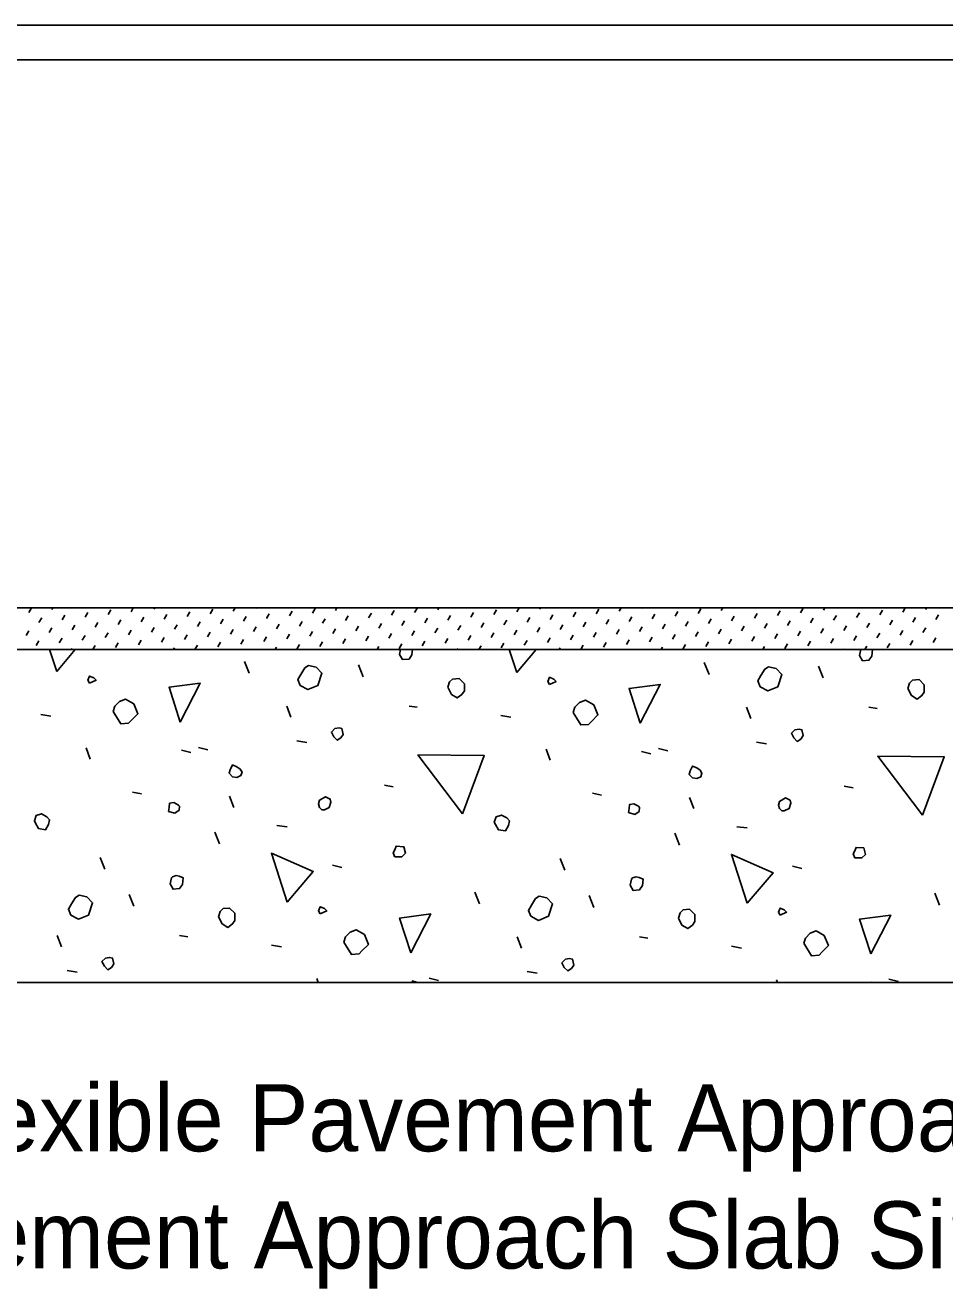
# Model space of a CAD drawing. Extents: x 0.5 to 40.8, y 1 to 25.8.
# Drawn here: x 26.642 to 29.406, y 9.64 to 13.435 of the extents above; entities that cross this region are included whole.
import ezdxf

# ---------------------------------------------------------------- set-up
doc = ezdxf.new("R2010")
doc.units = 0
for name, color, linetype in [('Dimension', 7, 'Continuous'), ('Miscellaneous', 7, 'Continuous'), ('TrafBarrierConc', 7, 'Continuous')]:
    doc.layers.add(name, color=color, linetype=linetype)

msp = doc.modelspace()

# ---------------------------------------------------------------- linework, layer by layer
at = {"layer": 'Miscellaneous'}
for p, q in [((26.6529, 11.6714), (26.6606, 11.6848)), ((26.6834, 11.6409), (26.6915, 11.6549)), ((26.7221, 11.6796), (26.7251, 11.6848)), ((26.7526, 11.649), (26.7607, 11.663)), ((26.8218, 11.6571), (26.8299, 11.6711)), ((26.8909, 11.6652), (26.899, 11.6792)), ((26.9601, 11.6733), (26.9667, 11.6848)), ((26.9906, 11.6428), (26.9987, 11.6568)), ((27.0293, 11.6814), (27.0312, 11.6848)), ((27.0598, 11.6509), (27.0679, 11.6649)), ((27.129, 11.659), (27.1371, 11.673)), ((27.1981, 11.6671), (27.2062, 11.6811)), ((27.2673, 11.6752), (27.2728, 11.6848)), ((27.2978, 11.6447), (27.3059, 11.6587)), ((27.3365, 11.6833), (27.3373, 11.6848)), ((27.367, 11.6528), (27.3751, 11.6668)), ((27.4361, 11.6609), (27.4442, 11.6749)), ((27.5053, 11.669), (27.5134, 11.683)), ((27.5358, 11.6385), (27.5439, 11.6524)), ((27.5745, 11.6771), (27.5789, 11.6848)), ((27.605, 11.6466), (27.6131, 11.6605)), ((27.6742, 11.6547), (27.6823, 11.6686)), ((27.7433, 11.6628), (27.7514, 11.6768)), ((27.8125, 11.6709), (27.8206, 11.6848)), ((27.843, 11.6403), (27.8511, 11.6543)), ((27.8817, 11.679), (27.885, 11.6848)), ((27.9122, 11.6484), (27.9203, 11.6624)), ((27.9814, 11.6565), (27.9895, 11.6705)), ((28.0505, 11.6646), (28.0586, 11.6786)), ((28.1197, 11.6727), (28.1267, 11.6848)), ((28.1502, 11.6422), (28.1583, 11.6562)), ((28.1888, 11.6808), (28.1911, 11.6848)), ((28.2194, 11.6503), (28.2275, 11.6643)), ((28.2885, 11.6584), (28.2966, 11.6724)), ((28.3577, 11.6665), (28.3658, 11.6805)), ((28.4269, 11.6746), (28.4328, 11.6848)), ((28.4574, 11.6441), (28.4655, 11.6581)), ((28.496, 11.6827), (28.4972, 11.6848)), ((28.5266, 11.6522), (28.5347, 11.6662)), ((28.5957, 11.6603), (28.6038, 11.6743)), ((28.6649, 11.6684), (28.673, 11.6824)), ((28.6954, 11.6379), (28.7035, 11.6519)), ((28.7341, 11.6765), (28.7389, 11.6848)), ((28.7646, 11.646), (28.7727, 11.66)), ((28.8032, 11.6846), (28.8033, 11.6848)), ((28.8337, 11.6541), (28.8419, 11.6681)), ((28.9029, 11.6622), (28.911, 11.6762)), ((28.9721, 11.6703), (28.9802, 11.6843)), ((29.0026, 11.6397), (29.0107, 11.6537)), ((29.0412, 11.6784), (29.045, 11.6848)), ((29.0718, 11.6478), (29.0799, 11.6618)), ((29.1409, 11.6559), (29.149, 11.6699)), ((29.2101, 11.664), (29.2182, 11.678)), ((29.2793, 11.6721), (29.2866, 11.6848)), ((29.3098, 11.6416), (29.3179, 11.6556)), ((29.3484, 11.6803), (29.3511, 11.6848)), ((29.379, 11.6497), (29.3871, 11.6637)), ((26.6448, 11.6023), (26.6529, 11.6163)), ((26.714, 11.6104), (26.7221, 11.6244)), ((26.7831, 11.6185), (26.7912, 11.6325)), ((26.8523, 11.6266), (26.8604, 11.6406)), ((26.9215, 11.6347), (26.9296, 11.6487)), ((26.952, 11.6042), (26.9601, 11.6182)), ((27.0212, 11.6123), (27.0293, 11.6263)), ((27.0903, 11.6204), (27.0984, 11.6344)), ((27.1595, 11.6285), (27.1676, 11.6425)), ((27.2287, 11.6366), (27.2368, 11.6506)), ((27.2592, 11.606), (27.2673, 11.62)), ((27.3283, 11.6141), (27.3365, 11.6281)), ((27.3975, 11.6222), (27.4056, 11.6362)), ((27.4667, 11.6303), (27.4748, 11.6443)), ((27.4972, 11.5998), (27.5053, 11.6138)), ((27.5664, 11.6079), (27.5745, 11.6219)), ((27.6355, 11.616), (27.6436, 11.63)), ((27.7047, 11.6241), (27.7128, 11.6381)), ((27.7739, 11.6322), (27.782, 11.6462)), ((27.8044, 11.6017), (27.8125, 11.6157)), ((27.8736, 11.6098), (27.8817, 11.6238)), ((27.9427, 11.6179), (27.9508, 11.6319)), ((28.0119, 11.626), (28.02, 11.64)), ((28.081, 11.6341), (28.0892, 11.6481)), ((28.1116, 11.6036), (28.1197, 11.6176)), ((28.1807, 11.6117), (28.1888, 11.6257)), ((28.2499, 11.6198), (28.258, 11.6338)), ((28.3191, 11.6279), (28.3272, 11.6419)), ((28.3882, 11.636), (28.3963, 11.65)), ((28.4188, 11.6055), (28.4269, 11.6194)), ((28.4879, 11.6136), (28.496, 11.6275)), ((28.5571, 11.6217), (28.5652, 11.6357)), ((28.6263, 11.6298), (28.6344, 11.6438)), ((28.6568, 11.5992), (28.6649, 11.6132)), ((28.726, 11.6073), (28.7341, 11.6213)), ((28.7951, 11.6154), (28.8032, 11.6294)), ((28.8643, 11.6235), (28.8724, 11.6375)), ((28.9334, 11.6316), (28.9415, 11.6456)), ((28.964, 11.6011), (28.9721, 11.6151)), ((29.0331, 11.6092), (29.0412, 11.6232)), ((29.1023, 11.6173), (29.1104, 11.6313)), ((29.1715, 11.6254), (29.1796, 11.6394)), ((29.2406, 11.6335), (29.2487, 11.6475)), ((29.2712, 11.603), (29.2793, 11.617)), ((29.3403, 11.6111), (29.3484, 11.6251)), ((26.6753, 11.5718), (26.6834, 11.5857)), ((26.7445, 11.5799), (26.7526, 11.5939)), ((26.8137, 11.588), (26.8218, 11.602)), ((26.8828, 11.5961), (26.8909, 11.6101)), ((26.9134, 11.5655), (26.9215, 11.5795)), ((26.9825, 11.5736), (26.9906, 11.5876)), ((27.0517, 11.5817), (27.0598, 11.5957)), ((27.1209, 11.5898), (27.129, 11.6038)), ((27.19, 11.5979), (27.1981, 11.6119)), ((27.2206, 11.5674), (27.2287, 11.5814)), ((27.2897, 11.5755), (27.2978, 11.5895)), ((27.3589, 11.5836), (27.367, 11.5976)), ((27.428, 11.5917), (27.4361, 11.6057)), ((27.4586, 11.5612), (27.4667, 11.5752)), ((27.5277, 11.5693), (27.5358, 11.5833)), ((27.5969, 11.5774), (27.605, 11.5914)), ((27.6661, 11.5855), (27.6742, 11.5995)), ((27.7352, 11.5936), (27.7433, 11.6076)), ((27.7658, 11.5631), (27.7739, 11.5771)), ((27.8349, 11.5712), (27.843, 11.5852)), ((27.9041, 11.5793), (27.9122, 11.5933)), ((27.9733, 11.5874), (27.9814, 11.6014)), ((28.0424, 11.5955), (28.0505, 11.6095)), ((28.0729, 11.5649), (28.081, 11.5789)), ((28.1421, 11.573), (28.1502, 11.587)), ((28.2113, 11.5811), (28.2194, 11.5951)), ((28.2804, 11.5892), (28.2885, 11.6032)), ((28.3496, 11.5973), (28.3577, 11.6113)), ((28.3801, 11.5668), (28.3882, 11.5808)), ((28.4493, 11.5749), (28.4574, 11.5889)), ((28.5185, 11.583), (28.5266, 11.597)), ((28.5876, 11.5911), (28.5957, 11.6051)), ((28.6873, 11.5687), (28.6954, 11.5827)), ((28.7565, 11.5768), (28.7646, 11.5908)), ((28.8256, 11.5849), (28.8337, 11.5989)), ((28.8948, 11.593), (28.9029, 11.607)), ((28.9253, 11.5625), (28.9334, 11.5765)), ((28.9945, 11.5706), (29.0026, 11.5846)), ((29.0637, 11.5787), (29.0718, 11.5927)), ((29.1328, 11.5868), (29.1409, 11.6008)), ((29.202, 11.5949), (29.2101, 11.6089)), ((29.2325, 11.5644), (29.2406, 11.5783)), ((29.3017, 11.5725), (29.3098, 11.5864)), ((29.3709, 11.5806), (29.379, 11.5946)), ((26.7811, 11.5598), (26.7831, 11.5633)), ((26.8456, 11.5598), (26.8523, 11.5714)), ((27.0872, 11.5598), (27.0903, 11.5652)), ((27.1517, 11.5598), (27.1595, 11.5733)), ((27.3933, 11.5598), (27.3975, 11.5671)), ((27.6349, 11.5598), (27.6355, 11.5609)), ((27.6994, 11.5598), (27.7047, 11.569)), ((27.941, 11.5598), (27.9427, 11.5627)), ((28.0055, 11.5598), (28.0119, 11.5708)), ((28.2471, 11.5598), (28.2499, 11.5646)), ((28.3116, 11.5598), (28.3191, 11.5727)), ((28.5532, 11.5598), (28.5571, 11.5665)), ((28.6182, 11.5606), (28.6263, 11.5746)), ((28.7948, 11.5598), (28.7951, 11.5603)), ((28.8593, 11.5598), (28.8643, 11.5684)), ((29.1009, 11.5598), (29.1023, 11.5621)), ((29.1654, 11.5598), (29.1715, 11.5702)), ((27.3148, 11.4887), (27.3006, 11.524)), ((27.6577, 11.4781), (27.6436, 11.5134)), ((28.6972, 11.4851), (28.683, 11.5205)), ((29.0401, 11.4745), (29.026, 11.5099)), ((27.4403, 11.3561), (27.4279, 11.3897)), ((27.7956, 11.3897), (27.8204, 11.3861)), ((28.8227, 11.3526), (28.8103, 11.3861)), ((29.178, 11.3861), (29.2028, 11.3826)), ((26.689, 11.3649), (26.7191, 11.3596)), ((28.0714, 11.3614), (28.1014, 11.3561)), ((27.458, 11.2854), (27.488, 11.2801)), ((28.8404, 11.2818), (28.8704, 11.2765)), ((26.8375, 11.2306), (26.8251, 11.2642)), ((27.1115, 11.2571), (27.1398, 11.25)), ((27.1628, 11.2659), (27.191, 11.2589)), ((28.2199, 11.227), (28.2075, 11.2606)), ((28.4939, 11.2536), (28.5222, 11.2465)), ((28.5452, 11.2624), (28.5734, 11.2553)), ((26.9648, 11.1316), (26.9913, 11.1263)), ((27.7214, 11.1528), (27.7479, 11.1475)), ((28.3472, 11.1281), (28.3737, 11.1227)), ((29.1038, 11.1493), (29.1303, 11.144)), ((27.2688, 11.0856), (27.2565, 11.1192)), ((28.6512, 11.0821), (28.6388, 11.1157)), ((27.2264, 10.976), (27.2123, 11.0114)), ((27.3979, 11.0308), (27.4297, 11.0273)), ((28.6088, 10.9725), (28.5947, 11.0078)), ((28.7803, 11.0273), (28.8121, 11.0238)), ((26.8817, 10.9), (26.8675, 10.9354)), ((28.2641, 10.8965), (28.2499, 10.9318)), ((27.5658, 10.9124), (27.5941, 10.9053)), ((28.9482, 10.9089), (28.9765, 10.9018)), ((26.9683, 10.7886), (26.9542, 10.824)), ((28.0078, 10.7957), (27.9936, 10.8311)), ((28.3507, 10.7851), (28.3366, 10.8205)), ((29.3901, 10.7922), (29.376, 10.8275)), ((26.7509, 10.6667), (26.7385, 10.7003)), ((27.1062, 10.7003), (27.1309, 10.6967)), ((27.382, 10.672), (27.412, 10.6667)), ((28.1333, 10.6631), (28.1209, 10.6967)), ((28.4886, 10.6967), (28.5133, 10.6932)), ((28.7644, 10.6684), (28.7944, 10.6631)), ((26.7685, 10.596), (26.7986, 10.5907)), ((28.1509, 10.5924), (28.181, 10.5871)), ((27.5223, 10.5598), (27.5181, 10.5712)), ((27.8045, 10.5641), (27.8218, 10.5598)), ((27.8557, 10.573), (27.884, 10.5659)), ((28.9034, 10.5598), (28.9005, 10.5677)), ((29.1869, 10.5606), (29.1901, 10.5598)), ((29.2381, 10.5694), (29.2664, 10.5624))]:
    msp.add_line(p, q, dxfattribs=at)
for points in [[(26.7367, 11.494), (26.7153, 11.5598)], [(26.7924, 11.5598), (26.7367, 11.494)], [(27.7673, 11.5452), (27.7762, 11.5293), (27.7956, 11.5311), (27.8045, 11.5435), (27.8059, 11.5598)], [(27.7702, 11.5598), (27.7673, 11.5452)], [(28.1191, 11.4904), (28.0966, 11.5598)], [(28.1778, 11.5598), (28.1191, 11.4904)], [(29.1497, 11.5417), (29.1586, 11.5258), (29.178, 11.5276), (29.1869, 11.5399), (29.1886, 11.5594), (29.1877, 11.5598)], [(29.1537, 11.5598), (29.1533, 11.5594), (29.1497, 11.5417)], [(27.4686, 11.4516), (27.4916, 11.4392), (27.5216, 11.4516), (27.534, 11.4887), (27.5163, 11.5064), (27.4933, 11.5117), (27.4827, 11.5046), (27.4704, 11.4851), (27.4615, 11.4692), (27.4686, 11.4516)], [(28.851, 11.448), (28.874, 11.4356), (28.904, 11.448), (28.9164, 11.4851), (28.8987, 11.5028), (28.8757, 11.5081), (28.8651, 11.5011), (28.8527, 11.4816), (28.8439, 11.4657), (28.851, 11.448)], [(26.8357, 11.4586), (26.8552, 11.4675), (26.8481, 11.4745), (26.8357, 11.4798), (26.8304, 11.4675), (26.8357, 11.4586)], [(27.9123, 11.4463), (27.9229, 11.425), (27.9406, 11.4144), (27.9547, 11.425), (27.9618, 11.4356), (27.9618, 11.4569), (27.9459, 11.4728), (27.9264, 11.471), (27.9176, 11.4622), (27.9123, 11.4463)], [(28.2181, 11.4551), (28.2376, 11.4639), (28.2305, 11.471), (28.2181, 11.4763), (28.2128, 11.4639), (28.2181, 11.4551)], [(29.2947, 11.4427), (29.3053, 11.4215), (29.323, 11.4109), (29.3371, 11.4215), (29.3442, 11.4321), (29.3442, 11.4533), (29.3283, 11.4692), (29.3088, 11.4675), (29.3, 11.4586), (29.2947, 11.4427)], [(27.108, 11.342), (27.0744, 11.4463), (27.1681, 11.4586), (27.108, 11.342)], [(28.4904, 11.3384), (28.4568, 11.4427), (28.5505, 11.4551), (28.4904, 11.3384)], [(26.9064, 11.3738), (26.9294, 11.3366), (26.9524, 11.3384), (26.9612, 11.3473), (26.9807, 11.3667), (26.9683, 11.3968), (26.9436, 11.4109), (26.9259, 11.4038), (26.9117, 11.3897), (26.9064, 11.3738)], [(28.2888, 11.3702), (28.3118, 11.3331), (28.3348, 11.3349), (28.3436, 11.3437), (28.3631, 11.3632), (28.3507, 11.3932), (28.326, 11.4074), (28.3083, 11.4003), (28.2941, 11.3861), (28.2888, 11.3702)], [(27.5693, 11.2978), (27.58, 11.2872), (27.5906, 11.2942), (27.5976, 11.3048), (27.5941, 11.3225), (27.5853, 11.3243), (27.5729, 11.3225), (27.5623, 11.3119), (27.5693, 11.2978)], [(28.9517, 11.2942), (28.9623, 11.2836), (28.973, 11.2907), (28.98, 11.3013), (28.9765, 11.319), (28.9677, 11.3207), (28.9553, 11.319), (28.9447, 11.3084), (28.9517, 11.2942)], [(27.9565, 11.0662), (27.8221, 11.243), (28.0219, 11.2412), (27.9565, 11.0662)], [(29.3389, 11.0626), (29.2045, 11.2394), (29.4043, 11.2377), (29.3389, 11.0626)], [(27.2653, 11.1776), (27.2777, 11.1758), (27.29, 11.1811), (27.2936, 11.1917), (27.2883, 11.2005), (27.2777, 11.2076), (27.2653, 11.2129), (27.2582, 11.1988), (27.2547, 11.1882), (27.2653, 11.1776)], [(28.6477, 11.174), (28.6601, 11.1722), (28.6724, 11.1776), (28.676, 11.1882), (28.6707, 11.197), (28.6601, 11.2041), (28.6477, 11.2094), (28.6406, 11.1952), (28.6371, 11.1846), (28.6477, 11.174)], [(27.0726, 11.0733), (27.0921, 11.0679), (27.1044, 11.0768), (27.1062, 11.0892), (27.1027, 11.0927), (27.0885, 11.0998), (27.0761, 11.098), (27.0744, 11.0856), (27.0726, 11.0733)], [(27.534, 11.0786), (27.5411, 11.0786), (27.5552, 11.0856), (27.5605, 11.1015), (27.5587, 11.1104), (27.5446, 11.1174), (27.5269, 11.1068), (27.5234, 11.0962), (27.5269, 11.0856), (27.534, 11.0786)], [(28.455, 11.0697), (28.4744, 11.0644), (28.4868, 11.0733), (28.4886, 11.0856), (28.4851, 11.0892), (28.4709, 11.0962), (28.4585, 11.0945), (28.4568, 11.0821), (28.455, 11.0697)], [(28.9164, 11.075), (28.9235, 11.075), (28.9376, 11.0821), (28.9429, 11.098), (28.9411, 11.1068), (28.927, 11.1139), (28.9093, 11.1033), (28.9058, 11.0927), (28.9093, 11.0821), (28.9164, 11.075)], [(26.6731, 11.0379), (26.6819, 11.022), (26.7031, 11.0185), (26.712, 11.0344), (26.7155, 11.0485), (26.7067, 11.0573), (26.6908, 11.0662), (26.6749, 11.0609), (26.6696, 11.045), (26.6731, 11.0379)], [(28.0555, 11.0344), (28.0643, 11.0185), (28.0855, 11.0149), (28.0944, 11.0308), (28.0979, 11.045), (28.0891, 11.0538), (28.0732, 11.0626), (28.0573, 11.0573), (28.0519, 11.0414), (28.0555, 11.0344)], [(27.7532, 10.9371), (27.7744, 10.9371), (27.785, 10.9477), (27.7797, 10.9672), (27.7567, 10.969), (27.7532, 10.9583), (27.7479, 10.9495), (27.7532, 10.9371), (27.7497, 10.9407)], [(27.4297, 10.801), (27.382, 10.9477), (27.5075, 10.8929), (27.4297, 10.801)], [(28.8121, 10.7975), (28.7644, 10.9442), (28.8899, 10.8894), (28.8121, 10.7975)], [(29.1356, 10.9336), (29.1568, 10.9336), (29.1674, 10.9442), (29.1621, 10.9637), (29.1391, 10.9654), (29.1356, 10.9548), (29.1303, 10.946), (29.1356, 10.9336), (29.1321, 10.9371)], [(27.0779, 10.8558), (27.0867, 10.8399), (27.1062, 10.8417), (27.115, 10.854), (27.1168, 10.8735), (27.1044, 10.8788), (27.0956, 10.8806), (27.085, 10.877), (27.0814, 10.8735), (27.0779, 10.8558)], [(28.4603, 10.8523), (28.4691, 10.8364), (28.4886, 10.8381), (28.4974, 10.8505), (28.4992, 10.87), (28.4868, 10.8753), (28.478, 10.877), (28.4674, 10.8735), (28.4638, 10.87), (28.4603, 10.8523)], [(26.7792, 10.7621), (26.8021, 10.7498), (26.8322, 10.7621), (26.8446, 10.7992), (26.8269, 10.8169), (26.8039, 10.8222), (26.7933, 10.8152), (26.7809, 10.7957), (26.7721, 10.7798), (26.7792, 10.7621)], [(28.1616, 10.7586), (28.1845, 10.7462), (28.2146, 10.7586), (28.227, 10.7957), (28.2093, 10.8134), (28.1863, 10.8187), (28.1757, 10.8116), (28.1633, 10.7922), (28.1545, 10.7763), (28.1616, 10.7586)], [(27.2229, 10.7568), (27.2335, 10.7356), (27.2512, 10.725), (27.2653, 10.7356), (27.2724, 10.7462), (27.2724, 10.7674), (27.2565, 10.7833), (27.237, 10.7816), (27.2282, 10.7727), (27.2229, 10.7568)], [(27.5287, 10.7657), (27.5481, 10.7745), (27.5411, 10.7816), (27.5287, 10.7869), (27.5234, 10.7745), (27.5287, 10.7657)], [(28.6053, 10.7533), (28.6159, 10.7321), (28.6335, 10.7215), (28.6477, 10.7321), (28.6548, 10.7427), (28.6548, 10.7639), (28.6388, 10.7798), (28.6194, 10.778), (28.6106, 10.7692), (28.6053, 10.7533)], [(28.9111, 10.7621), (28.9305, 10.771), (28.9235, 10.778), (28.9111, 10.7833), (28.9058, 10.771), (28.9111, 10.7621)], [(27.8009, 10.649), (27.7673, 10.7533), (27.861, 10.7657), (27.8009, 10.649)], [(29.1833, 10.6455), (29.1497, 10.7498), (29.2434, 10.7621), (29.1833, 10.6455)], [(27.5994, 10.6808), (27.6224, 10.6437), (27.6454, 10.6455), (27.6542, 10.6543), (27.6736, 10.6737), (27.6613, 10.7038), (27.6365, 10.7179), (27.6188, 10.7109), (27.6047, 10.6967), (27.5994, 10.6808)], [(28.9818, 10.6773), (29.0048, 10.6401), (29.0278, 10.6419), (29.0366, 10.6508), (29.056, 10.6702), (29.0437, 10.7003), (29.0189, 10.7144), (29.0012, 10.7073), (28.9871, 10.6932), (28.9818, 10.6773)], [(26.8799, 10.6083), (26.8905, 10.5977), (26.9011, 10.6048), (26.9082, 10.6154), (26.9047, 10.6331), (26.8958, 10.6348), (26.8835, 10.6331), (26.8728, 10.6225), (26.8799, 10.6083)], [(28.2623, 10.6048), (28.2729, 10.5942), (28.2835, 10.6013), (28.2906, 10.6119), (28.2871, 10.6295), (28.2782, 10.6313), (28.2658, 10.6295), (28.2552, 10.6189), (28.2623, 10.6048)]]:
    msp.add_lwpolyline(points, dxfattribs=at)
at = {"layer": 'TrafBarrierConc'}
for p, q in [((23.987, 13.4349), (37.3177, 13.4349)), ((23.987, 13.3307), (37.3177, 13.3307)), ((23.987, 11.6848), (39.8181, 11.6848)), ((23.987, 11.5598), (39.8181, 11.5598)), ((23.987, 10.5598), (39.8181, 10.5598))]:
    msp.add_line(p, q, dxfattribs=at)

# ---------------------------------------------------------------- texts
at = {"layer": 'Dimension'}
for s, p in [('Approach Slab (Flexible Pavement Approach Slab ', (24.3764, 10.0525)), ('Shown, Rigid Pavement Approach Slab Similar)', (24.3764, 9.7005))]:
    msp.add_text(s, height=0.2016, dxfattribs=at).set_placement(p)

doc.saveas('drawing.dxf')
